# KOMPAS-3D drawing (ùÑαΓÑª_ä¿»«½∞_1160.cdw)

Referenced files: Чертеж_Диполь_1160.cdw
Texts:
  Коаксиальные диполи
  Edik
  Противовес
  (латунь)
  Вибратор
  RG-316
  SMA
  Кожух
  Антенна TX
  Антенна RX
  Ethnocentric
Dimensions and other numbers on the sheet: 1160МГЦ; 63; 58; 40,5; 6; 19,5; 161,5; 14; 35; 55; 59,3; 1,5; 1:1; 1; 1160МГЦ-; 0; 2; 3; 4; 5; 7; 8; 9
